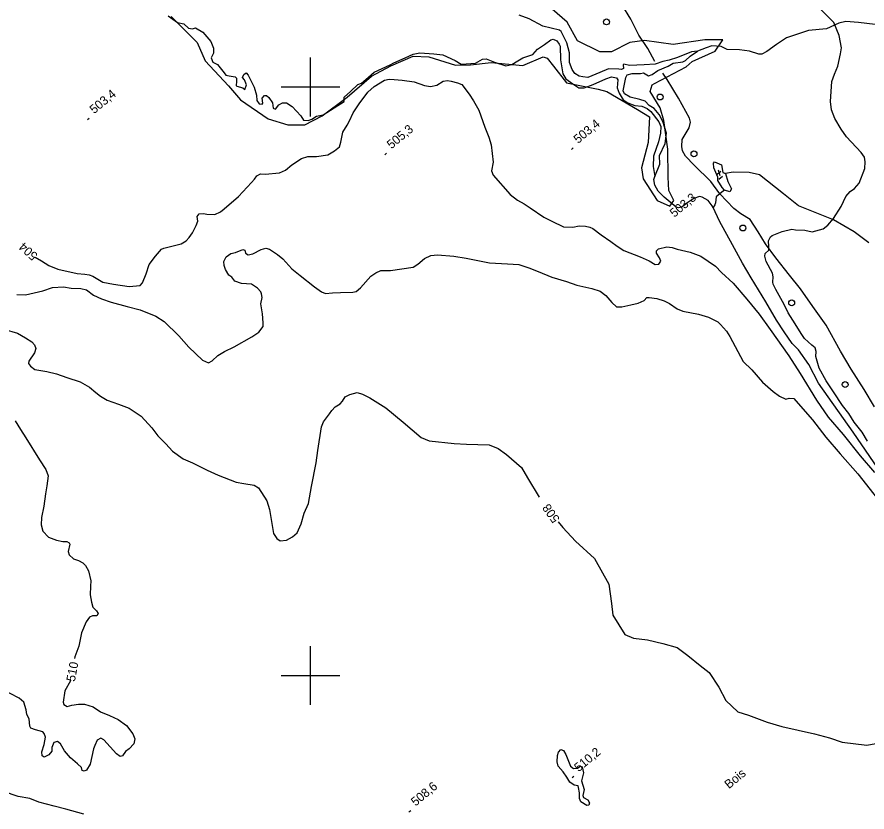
# Model space of a CAD drawing. Extents: x 347059 to 352153, y 6073752 to 6078601.
# Drawn here: x 348150.4 to 348583.7, y 6076130.4 to 6076535.6 of the extents above; entities that cross this region are included whole.
import ezdxf

# ---------------------------------------------------------------- set-up
doc = ezdxf.new("R2010")
doc.units = 0
for name, color, linetype in [('Level 1', 7, 'Continuous'), ('Level 2', 7, 'Continuous'), ('Level 22', 7, 'Continuous'), ('Level 3', 7, 'Continuous'), ('Level 36', 7, 'Continuous'), ('Level 4', 7, 'Continuous'), ('Level 44', 7, 'Continuous'), ('Level 61', 7, 'Continuous')]:
    doc.layers.add(name, color=color, linetype=linetype)

msp = doc.modelspace()

# ---------------------------------------------------------------- linework, layer by layer
at = {"layer": 'Level 1'}
for points in [[(348149.41, 6076329.83), (348152.14, 6076325.41), (348154.95, 6076321.2), (348161.89, 6076309.85), (348165.02, 6076304.97), (348166.31, 6076301.74), (348165.64, 6076296.69), (348164.83, 6076292.61), (348164, 6076286.33), (348162.91, 6076280.52), (348162.77, 6076276.74), (348163.63, 6076273.55), (348166.45, 6076270.43), (348170.56, 6076268.97), (348173.78, 6076268.22), (348175.83, 6076268.36), (348176.94, 6076267.7), (348177.32, 6076266.94), (348176.39, 6076263.15), (348176.92, 6076261.58), (348179.1, 6076259.53), (348181.8, 6076258.61), (348183.97, 6076257.5), (348185.24, 6076256.02), (348186.86, 6076253.36), (348188.09, 6076248.32), (348187.88, 6076245.57), (348187.7, 6076241.07)], [(348187.7, 6076241.07), (348188.29, 6076237.38), (348189.05, 6076234.78), (348190.94, 6076232.89), (348191.72, 6076231.53), (348191.13, 6076230.48), (348188.93, 6076230.35), (348187.37, 6076229.81), (348185.66, 6076227.39), (348183.34, 6076221.73), (348181.89, 6076214.92), (348179.89, 6076209.54), (348179.73, 6076208.6)], [(348177.72, 6076197.59), (348177.67, 6076197.33), (348174.74, 6076192.23), (348173.88, 6076186.47), (348174.23, 6076185.28), (348175.9, 6076184.29), (348178.41, 6076184.83), (348181.65, 6076185.32), (348184.86, 6076185.37), (348189.2, 6076184.1), (348193.02, 6076181.56), (348197.45, 6076179.56), (348202.03, 6076177.55), (348206.17, 6076174.48), (348209.5, 6076170.3), (348210.4, 6076167.68), (348209.92, 6076165.1), (348207.62, 6076162.58), (348205.69, 6076161.19), (348204.15, 6076159.05), (348202.89, 6076158.78), (348201.17, 6076160.14), (348197.94, 6076163.58), (348194.64, 6076167.25), (348193.03, 6076168.02), (348191.28, 6076167.06), (348190.06, 6076164.39), (348189.34, 6076162.55), (348187.68, 6076154.88), (348185.85, 6076151.81), (348184.57, 6076151.25), (348183.65, 6076151.54), (348183.19, 6076153.18), (348181.28, 6076154.92), (348177.58, 6076157.96), (348174.51, 6076161.68), (348172.58, 6076165.17), (348171, 6076166.38), (348169.22, 6076165.93), (348168.16, 6076163.39), (348168.08, 6076161.43), (348166.64, 6076159.64), (348164.29, 6076158.43), (348163.18, 6076159.1), (348162.96, 6076161.08), (348164.19, 6076164.85), (348164.97, 6076168.5), (348164.24, 6076170.45), (348163.57, 6076171.22), (348159.73, 6076172.38), (348157.39, 6076173.21), (348156.88, 6076174.12), (348156.5, 6076177.86)], [(348156.5, 6076177.86), (348155.36, 6076180.13), (348155.1, 6076182.48), (348153.79, 6076186.36), (348151.47, 6076188.42), (348142.36, 6076193.17)], [(348428.87, 6076150.93), (348426.3, 6076153.75), (348425.67, 6076156.05), (348425.91, 6076159.24), (348426.33, 6076160.96), (348427.52, 6076162.26), (348428.95, 6076161.86), (348430.19, 6076159.8), (348432.51, 6076153.8), (348434.1, 6076152.59), (348436.16, 6076152.73), (348437.63, 6076153.86), (348438.48, 6076153.5), (348439.12, 6076150.39), (348438.48, 6076147.67), (348438.09, 6076146.39), (348439.43, 6076141.84), (348438.77, 6076138.83), (348439.13, 6076137.78), (348441.38, 6076136.59), (348442.28, 6076135.07), (348441.91, 6076133.93), (348440.8, 6076133.79), (348437.8, 6076135.69), (348437.12, 6076137.27), (348437.11, 6076140.12), (348436.67, 6076142.99), (348436.37, 6076143.82), (348434.41, 6076144.03), (348432.27, 6076145.72), (348430.64, 6076148.25), (348428.87, 6076150.93)]]:
    msp.add_lwpolyline(points, dxfattribs=at)
at = {"layer": 'Level 2'}
for points in [[(348579.7, 6076450.91), (348582.54, 6076458.4), (348582.79, 6076461.76), (348582.46, 6076464.2), (348580.72, 6076466.53), (348573.16, 6076474.48), (348570.45, 6076478.41), (348567.33, 6076483.91), (348565.53, 6076488.37), (348565.11, 6076492.5), (348565.8, 6076502.79), (348567.03, 6076506.44), (348568.88, 6076510.49), (348570.23, 6076516.84), (348570.61, 6076519.89), (348569.47, 6076526.28), (348566.81, 6076532.85), (348562.83, 6076536.65), (348556.15, 6076543.58), (348553.8, 6076546.61), (348552.44, 6076548.98), (348551.14, 6076550.32)], [(348159.68, 6076413.27), (348162.95, 6076411.28), (348166.66, 6076409.04), (348171.27, 6076407.17), (348181.12, 6076404.92), (348184.97, 6076404.57), (348187.21, 6076404.19), (348189.05, 6076403.47), (348194.09, 6076400.47), (348199.65, 6076399.41), (348207.54, 6076398.32), (348213.2, 6076398.71), (348214.4, 6076400.16), (348216.14, 6076404.79), (348217.72, 6076409.43), (348220.9, 6076413.81), (348224.08, 6076417.24), (348225.3, 6076417.88), (348234.09, 6076420.02), (348236.62, 6076421.52), (348238.07, 6076423.32), (348239.78, 6076425.61), (348241.74, 6076429.34), (348242.49, 6076431.63), (348242.15, 6076433.92), (348243.28, 6076435.31), (348245.42, 6076435.52), (348247.22, 6076435.17), (348251.23, 6076434.95), (348254.04, 6076436.28), (348255.98, 6076437.83), (348263.25, 6076444.1), (348269.86, 6076451.31), (348271.45, 6076452.95), (348272.6, 6076454.62), (348274.58, 6076455.65), (348276.91, 6076455.48), (348284.21, 6076456.2), (348287.24, 6076457.59), (348290.45, 6076460.36), (348295.37, 6076463.52), (348298.66, 6076464.45), (348303.13, 6076464.49), (348308.76, 6076465.41), (348312.21, 6076467.43), (348314.7, 6076469.44), (348315.47, 6076471.88), (348316.43, 6076476.93), (348318.67, 6076480.5), (348319.93, 6076482.68), (348321.78, 6076486.86), (348324.75, 6076491.34), (348329.3, 6076497.3), (348332.52, 6076500.22), (348337.74, 6076503.36), (348340.12, 6076503.92), (348342.68, 6076503.81), (348346.76, 6076503.51), (348352.77, 6076502.57), (348358.05, 6076500.73), (348361.17, 6076500.28)], [(348361.17, 6076500.28), (348364.36, 6076500.86), (348367.6, 6076502.97), (348369.89, 6076503.31), (348371.7, 6076502.97), (348374.93, 6076502.07), (348377.21, 6076501.18), (348380.88, 6076496.3), (348383.11, 6076492.92), (348385.84, 6076488.18), (348388.79, 6076479.55), (348390.96, 6076474.34), (348392.07, 6076470.52), (348393.09, 6076461.59), (348392.33, 6076457.25), (348393.04, 6076455), (348401.76, 6076445.22), (348405.57, 6076442.23), (348408.89, 6076440.46), (348412.03, 6076438.4), (348419.01, 6076433.65), (348423.03, 6076431.52), (348428.9, 6076428.68), (348433.73, 6076428.48), (348437, 6076429.12), (348440.22, 6076429.04), (348442.39, 6076428.59), (348443.95, 6076427.89), (348448.11, 6076424.66), (348453.07, 6076421.29), (348456.33, 6076418.79), (348459.76, 6076416.56), (348468.1, 6076413.39), (348472.64, 6076411.31), (348475.67, 6076409.55), (348477.59, 6076409.7), (348478.5, 6076411.17), (348477.82, 6076412.91), (348476.38, 6076415.21), (348476.4, 6076416.45), (348477.43, 6076417.48), (348481.68, 6076418.42), (348484.3, 6076418.08), (348486.89, 6076417.31)], [(348583.99, 6076319.52), (348581.24, 6076323.97), (348577.14, 6076329.18), (348574.38, 6076333.49), (348571.16, 6076337.54), (348566.61, 6076344.54), (348562.78, 6076350.24), (348559.29, 6076356.65), (348557.6, 6076362.56), (348557.8, 6076365.19), (348557.2, 6076366.99), (348555.54, 6076368.43), (348551.83, 6076371.78), (348550.1, 6076374.25), (348547.03, 6076379.24), (348543.47, 6076384.77), (348541.45, 6076389.17), (348537.18, 6076396.81), (348535.76, 6076399.41), (348535.62, 6076400.51), (348535.81, 6076403.14), (348535.45, 6076405.14), (348532.29, 6076411.02), (348531.61, 6076413.7), (348531.71, 6076415.02), (348533.7, 6076416.73), (348533.67, 6076418.61), (348533.45, 6076421.56), (348534.55, 6076423.61), (348535.41, 6076424.2), (348540.41, 6076426.33), (348545.34, 6076427.44), (348547.3, 6076427.08), (348552.06, 6076426.96), (348555.67, 6076426.11), (348561.29, 6076427.68), (348563.78, 6076429.55), (348566.61, 6076432.94), (348570.44, 6076438.97), (348572.81, 6076444.15), (348575.05, 6076446.63), (348577.23, 6076448.23), (348579.7, 6076450.91)], [(348275.9, 6076379.82), (348275.51, 6076384.38), (348274.72, 6076389.4), (348275.33, 6076392.65), (348274.95, 6076394.5), (348274.66, 6076395.47), (348273.06, 6076397.49), (348269.91, 6076399.39), (348264.9, 6076399.83), (348261.48, 6076400.96), (348259.81, 6076403.05), (348258.35, 6076404.11), (348256.65, 6076406.86), (348255.93, 6076408.96), (348255.87, 6076411.08), (348256.92, 6076413.34), (348259.46, 6076415.13), (348261.69, 6076415.55), (348265.53, 6076417.1), (348266.52, 6076416.74), (348266.78, 6076415.33), (348268.25, 6076414.42), (348270.55, 6076414.91), (348274.89, 6076417.15), (348277.28, 6076417.86), (348279.13, 6076417.28), (348283.18, 6076414.65), (348285.93, 6076412.41), (348290.45, 6076407.33), (348294.8, 6076403.87), (348302.05, 6076398.16), (348305.58, 6076395.49), (348307.72, 6076394.75), (348311.25, 6076395.08), (348315.21, 6076395.23), (348321.59, 6076395.42), (348323.29, 6076395.67), (348325.55, 6076397.62)], [(348486.89, 6076417.31), (348493.59, 6076415.72), (348498.95, 6076413.8), (348506.42, 6076408.64), (348509.56, 6076405.48), (348515.46, 6076399.92), (348522.34, 6076391.8), (348528.75, 6076384.23), (348534.26, 6076376.43), (348543.83, 6076362.98), (348549.54, 6076353.99), (348557.86, 6076340.41), (348563.81, 6076331.62), (348571.53, 6076322.85), (348580.2, 6076312.03), (348587.57, 6076303.5)], [(348325.55, 6076397.62), (348330.67, 6076403.54), (348333.22, 6076405.32), (348335.86, 6076406.38), (348340.84, 6076406.45), (348352.3, 6076408.18), (348354.75, 6076409.61), (348358.11, 6076412.51), (348361.3, 6076414.03), (348364.77, 6076414.44), (348372.98, 6076413.77), (348379.41, 6076412.65), (348391.32, 6076410.4), (348400.42, 6076409.81), (348406.18, 6076409.47), (348411.25, 6076407.71), (348416.02, 6076405.97), (348422.97, 6076402.98), (348430.57, 6076400.82), (348435.71, 6076398.99), (348443.42, 6076397.33), (348447.7, 6076395.85), (348450.48, 6076393.75), (348453.64, 6076390.08), (348455.9, 6076387.94), (348458.76, 6076387.96), (348463.29, 6076388.87), (348467.02, 6076389.77), (348470.06, 6076391.16), (348471.49, 6076392.66), (348472.67, 6076392.72), (348476.51, 6076392.23), (348480.3, 6076391), (348483.05, 6076389.56), (348486.88, 6076386.87), (348489.72, 6076385.64), (348497.75, 6076384.25), (348502.9, 6076382.56), (348507.71, 6076380.31), (348509.01, 6076378.97)], [(348150.35, 6076394.2), (348154.78, 6076393.95), (348163.62, 6076396.01), (348168.42, 6076397.71), (348174.13, 6076398.02), (348178.03, 6076397.45), (348182.91, 6076397.31), (348185.77, 6076396.52), (348189.38, 6076393.92), (348193.39, 6076391.95), (348198.38, 6076390.27), (348206.46, 6076388.01), (348213.2, 6076386.35), (348221.22, 6076383.21), (348225.32, 6076380.5), (348232.95, 6076373.08), (348238.01, 6076367.38), (348244.88, 6076360.67), (348248.01, 6076359.42), (348249.9, 6076360.38), (348252.74, 6076363.09), (348256.11, 6076365.18), (348261.11, 6076367.6), (348270.11, 6076372.64), (348273.72, 6076375.08), (348275.91, 6076377.92), (348275.9, 6076379.82)], [(348143.72, 6076376.59), (348150.7, 6076374.48), (348154.75, 6076372.15)], [(348509.01, 6076378.97), (348511.98, 6076375.53), (348513.67, 6076372.78), (348520.49, 6076359.99), (348524.94, 6076355.79), (348530.48, 6076349.53), (348535.91, 6076344.67), (348539.11, 6076342.39), (348542.22, 6076340.84), (348544.02, 6076341.3), (348546.35, 6076341.13), (348548.66, 6076338.62), (348555.88, 6076330.26), (348562.63, 6076321.5), (348570.07, 6076313.05), (348579.06, 6076302.81), (348588.96, 6076290.08)], [(348154.75, 6076372.15), (348157.88, 6076370.1), (348159.29, 6076368.46), (348159.95, 6076366.59), (348159.29, 6076364.53), (348156.34, 6076360.22), (348156.32, 6076358.98), (348157.24, 6076357.6), (348159.53, 6076356.05), (348165.57, 6076355.03), (348170.44, 6076353.8), (348175.84, 6076351.95), (348182.52, 6076349.71), (348187.28, 6076347.03), (348190.57, 6076344.17), (348192.91, 6076342.39), (348196.26, 6076340.4), (348202.09, 6076338.37), (348207.62, 6076336.21), (348213.73, 6076332.12), (348219.05, 6076326.26), (348222.24, 6076322.09), (348226.17, 6076318.01), (348229.69, 6076314.4), (348235.16, 6076310.43), (348239.81, 6076308.34), (348247.27, 6076304.58), (348252.99, 6076302.05), (348262.13, 6076298.54), (348266.02, 6076297.81), (348271.29, 6076297.06), (348273.52, 6076295.59), (348277.7, 6076289.01), (348279.11, 6076284.53), (348281.2, 6076272.34), (348282.77, 6076269.89), (348284.5, 6076268.67), (348287.74, 6076269.01), (348290.78, 6076270.69), (348293.12, 6076272.7), (348295.22, 6076277.36), (348296.79, 6076282.79), (348298.91, 6076287.75), (348300.58, 6076296.38), (348302.86, 6076308.4), (348303.76, 6076314.6), (348305.62, 6076326.8), (348306.69, 6076329.35), (348309.61, 6076333.37), (348310.84, 6076335.1), (348312.65, 6076336.94), (348315.17, 6076338.43), (348316.38, 6076339.88), (348317.7, 6076341.97), (348319.99, 6076343.26), (348323.72, 6076344.3), (348326.42, 6076343.38), (348330.22, 6076341.49), (348338.32, 6076336.43), (348347.25, 6076329.2), (348356.49, 6076321.26), (348360.48, 6076319.65), (348373.21, 6076318.27), (348379.53, 6076317.89), (348391.05, 6076317.59)], [(348391.05, 6076317.59), (348395.7, 6076315.72), (348399.85, 6076312.67), (348407.48, 6076306.01), (348410.53, 6076300.69), (348416.63, 6076290.87)], [(348426.22, 6076278.3), (348428.61, 6076275.37), (348435.16, 6076268.48), (348444.84, 6076259.65), (348452.05, 6076246.62), (348453.41, 6076236.62), (348454.05, 6076230.77), (348460.26, 6076220.88), (348464.66, 6076218.96), (348471.77, 6076218.19), (348479.59, 6076216.29), (348486.91, 6076214.2), (348492.32, 6076210.18), (348498.57, 6076205.16), (348503.16, 6076201.58), (348508.14, 6076194.05), (348511.69, 6076187.34), (348517.87, 6076181.51), (348523.18, 6076179.75), (348532.73, 6076176.16), (348540.24, 6076174.01), (348556.85, 6076170.22), (348564.58, 6076168.26), (348570.99, 6076166.08), (348583.59, 6076164.47), (348590.05, 6076165.72)]]:
    msp.add_lwpolyline(points, dxfattribs=at)
at = {"layer": 'Level 22'}
for points in [[(348475.53, 6076513.03), (348471.95, 6076519.53), (348467.38, 6076526.4), (348463.23, 6076534.46), (348458.68, 6076542.03), (348454.94, 6076548.54), (348449.63, 6076556.91), (348445.15, 6076563.4), (348442, 6076568.67), (348438.97, 6076574.34), (348436.39, 6076578.65), (348434.44, 6076582.57)], [(348587.41, 6076336.94), (348582.21, 6076345.8), (348575.54, 6076356.15), (348570.15, 6076365.24), (348562.79, 6076378.55), (348556.13, 6076388.08), (348549.82, 6076397.01), (348544.1, 6076404.09), (348537.25, 6076412.95), (348531.97, 6076419.95), (348528.2, 6076426.13), (348524.11, 6076432.34), (348519.38, 6076435.29), (348515.85, 6076438.05), (348508.58, 6076445.52), (348504.14, 6076451.72), (348495.53, 6076460.16), (348491.22, 6076464.75), (348489.57, 6076467.44), (348489.3, 6076469.63), (348489.44, 6076473.14), (348493.09, 6076479.17), (348493.62, 6076482.03), (348493.22, 6076484.03), (348487.5, 6076494.18), (348481.77, 6076503.78), (348479.62, 6076506.95)], [(348184.42, 6076129.32), (348175.2, 6076131.94), (348169.4, 6076133.38), (348161.45, 6076135.46), (348156.87, 6076137.33), (348150.91, 6076138.41), (348143.49, 6076140.96)]]:
    msp.add_lwpolyline(points, dxfattribs=at)
at = {"layer": 'Level 3'}
for p, q in [((348186.33, 6076483.33), (348187.25, 6076484.1)), ((348433.03, 6076468.17), (348433.95, 6076468.94)), ((348337.85, 6076465.42), (348338.77, 6076466.19)), ((348507.36, 6076455.52), (348509.17, 6076457.01)), ((348507.82, 6076457.65), (348508.65, 6076454.9)), ((348508.08, 6076453), (348509.93, 6076454.53)), ((348433.34, 6076147.94), (348434.26, 6076148.71)), ((348350.16, 6076130.47), (348351.08, 6076131.24))]:
    msp.add_line(p, q, dxfattribs=at)
at = {"layer": 'Level 36'}
for centre in [(348450.88, 6076533.12), (348478.22, 6076494.87), (348495.47, 6076465.86), (348520.39, 6076428.08), (348545.27, 6076389.91), (348572.55, 6076348.28)]:
    msp.add_circle(centre, 1.5, dxfattribs=at)
at = {"layer": 'Level 4'}
for points in [[(348227.44, 6076536.16), (348232.24, 6076532.79), (348235.5, 6076532.14), (348237.74, 6076529.93), (348239.8, 6076529.63), (348241.36, 6076530.11), (348245.03, 6076527.9), (348249.14, 6076523.19), (348250.52, 6076519.67), (348250.47, 6076517.21), (348249.28, 6076514.77), (348250.29, 6076512.67), (348252.61, 6076511.45), (348255.94, 6076507.22), (348256.86, 6076506.03), (348258.55, 6076505.64), (348261.59, 6076505.17)], [(348479.56, 6076482.43), (348477.72, 6076485.87), (348475.12, 6076488.96), (348472.67, 6076490.45), (348470.57, 6076492.76), (348467.94, 6076493.56), (348462.98, 6076494.81), (348460.13, 6076496.42), (348459.4, 6076497.99), (348460.66, 6076504.73), (348461.48, 6076506.09), (348463.91, 6076506.78), (348468.29, 6076506.85), (348469.71, 6076507.22), (348472.35, 6076505.59), (348474.21, 6076506.25), (348477.05, 6076508.34), (348482.31, 6076510.58), (348484.85, 6076512.12), (348489.74, 6076512.85), (348491.13, 6076513.42), (348493.5, 6076515.71), (348497.35, 6076518.2), (348494.21, 6076517.82), (348487.05, 6076514.96), (348482.85, 6076513.61), (348479.68, 6076512.9), (348475.64, 6076511.53), (348470.05, 6076511.28), (348462.53, 6076510.83), (348459.77, 6076511.61), (348459.38, 6076511.27), (348459.51, 6076509.42), (348458.6, 6076508.88), (348457.1, 6076508.97), (348451.88, 6076509.18), (348447.54, 6076507.26), (348441.28, 6076504.86), (348438.85, 6076505.07), (348436.87, 6076505.45), (348434.82, 6076506.81), (348433.32, 6076508.95), (348431.99, 6076512.51), (348431.95, 6076517.39), (348430.58, 6076522.51), (348427.79, 6076528.16), (348426.95, 6076528.89), (348418.49, 6076530.98), (348411.48, 6076534.67), (348406.28, 6076536.64)], [(348587.83, 6076531.75), (348579.4, 6076532.85), (348572.82, 6076533.26), (348569.24, 6076532.43), (348563.05, 6076529.62), (348553.87, 6076528.74), (348542.64, 6076524.93), (348537.5, 6076521.58), (348532.54, 6076518), (348530.14, 6076516.65), (348528.54, 6076516.67), (348523.74, 6076518.27), (348518.64, 6076518.88), (348512.44, 6076519.1), (348509.26, 6076520.56), (348504.5, 6076520.85), (348501.64, 6076519.96), (348497.35, 6076518.2)], [(348362.8, 6076516.78), (348367.4, 6076516.42), (348373.66, 6076513.54), (348376.78, 6076511.62), (348379.28, 6076511.69), (348384.06, 6076512.1), (348387.64, 6076514.2), (348389.57, 6076514.32), (348393.81, 6076512.6), (348399.54, 6076510.71), (348402.59, 6076511.38), (348405.66, 6076513.37), (348408.2, 6076514.83), (348413.3, 6076516.56), (348415.78, 6076519.25), (348419.33, 6076521.56), (348422.52, 6076523.95), (348423.66, 6076524.38), (348425.54, 6076523.4), (348426.68, 6076521.78), (348427.32, 6076520.74), (348427.51, 6076513.72), (348428.63, 6076506.74), (348430.22, 6076504.14), (348433.69, 6076501.63), (348436.82, 6076499.51), (348439.49, 6076499.56), (348444.13, 6076501.29), (348450.51, 6076504.1), (348453.5, 6076505.19), (348456.03, 6076504.6), (348456.68, 6076503.56), (348456.38, 6076499.53), (348457.29, 6076496.74), (348459.42, 6076493.4), (348461.67, 6076491.9), (348465.39, 6076490.51), (348468.89, 6076490.2), (348471.61, 6076489.02), (348473.52, 6076487.46), (348477.49, 6076482.12), (348478.52, 6076479.82), (348478.47, 6076476.38), (348477.33, 6076472.01), (348474.91, 6076464.77), (348474.71, 6076459.46), (348475.51, 6076454.39), (348478.08, 6076460.56), (348477.92, 6076464.96), (348480.86, 6076471.22), (348481.38, 6076476.41), (348479.56, 6076482.43)], [(348261.59, 6076505.17), (348262.35, 6076504.45), (348262.24, 6076502.69), (348262.03, 6076500.7), (348262.36, 6076500.3), (348265.57, 6076499.45), (348266.45, 6076498.68), (348267.39, 6076501.14), (348266.33, 6076503.57), (348265.41, 6076504.75), (348265.99, 6076506.3), (348267.17, 6076507.14), (348268.25, 6076505.94), (348271.22, 6076499.82), (348272.44, 6076495.86), (348272.65, 6076493.01), (348273.86, 6076491.3), (348275.28, 6076491.14), (348275.66, 6076491.76), (348275.41, 6076494.2), (348276.47, 6076495.55), (348277.55, 6076495.7), (348278.77, 6076494.61), (348280.55, 6076491.87), (348281.01, 6076489.08), (348282.2, 6076488.65), (348283.83, 6076490.93), (348285.71, 6076491.91), (348287.84, 6076491.89), (348290.63, 6076489.93), (348295.02, 6076485.24), (348296.48, 6076483.06), (348298.84, 6076482.86), (348300.65, 6076483.48), (348303.05, 6076485.12), (348306.43, 6076485.85), (348310.14, 6076488.07), (348317.08, 6076492.63), (348317.19, 6076494.84), (348320.42, 6076497.71), (348324.05, 6076501.29), (348325.99, 6076501.94), (348328.16, 6076503.85), (348332.52, 6076507.44), (348340.67, 6076511.29), (348342.46, 6076512.19), (348348.26, 6076514.89), (348352.27, 6076516.75), (348355.8, 6076517.31), (348362.8, 6076516.78)], [(348513.73, 6076446.46), (348511.11, 6076447.35), (348509.79, 6076448.65), (348507.65, 6076452.36), (348507.55, 6076454.08), (348505.62, 6076458.8), (348505.45, 6076461.15), (348505.95, 6076461.8), (348509.42, 6076460.27), (348510.12, 6076456.4), (348511.46, 6076455.87), (348512.75, 6076451.75), (348514.52, 6076448.11), (348513.73, 6076446.46)], [(348593.64, 6076299.17), (348576.64, 6076324.03), (348558.99, 6076348.96), (348554.08, 6076358.56), (348548.83, 6076366.05), (348545.58, 6076369.2), (348541.43, 6076375.21), (348537.51, 6076381.03), (348532.05, 6076390.39), (348524.63, 6076402.62), (348520.23, 6076410.09), (348515.06, 6076419.47), (348508.48, 6076431.59), (348505.18, 6076438.49), (348504.73, 6076439.45), (348502.78, 6076442.03), (348499.7, 6076443.82), (348498.26, 6076444.19), (348495.43, 6076443.08), (348492.27, 6076441.1), (348489.43, 6076438.85), (348487.63, 6076438.39), (348486.31, 6076438.79), (348480.2, 6076443.83), (348477.28, 6076446.82), (348475.46, 6076449.89), (348475.05, 6076452.79), (348475.51, 6076454.39)], [(348584.62, 6076420.48), (348577.1, 6076426.21), (348566.6, 6076432.27), (348548.83, 6076439.46), (348541.09, 6076445.45), (348528.83, 6076455.11), (348523.55, 6076456.39), (348515.47, 6076456.6), (348511.46, 6076455.87)], [(348511.11, 6076447.35), (348509.59, 6076446.29), (348508.58, 6076445.52), (348506.74, 6076443.96), (348506.44, 6076440.99), (348506.14, 6076439.83), (348505.18, 6076438.49)]]:
    msp.add_lwpolyline(points, dxfattribs=at)
at = {"layer": 'Level 44'}
msp.add_lwpolyline([(348228.91, 6076535.91), (348242.3, 6076522.69), (348246.25, 6076513.33), (348258.27, 6076500.48), (348264.39, 6076493.39), (348278.4, 6076483.72), (348288.46, 6076480.72), (348297.06, 6076480.71), (348305.96, 6076485.18), (348318.73, 6076494.72), (348331.1, 6076505.45), (348340.89, 6076510.82), (348352.27, 6076515.73), (348360.26, 6076515.36), (348373.98, 6076511.06), (348381.52, 6076511.22), (348392.09, 6076512.43), (348408.25, 6076510.94), (348418.59, 6076515.28), (348420.59, 6076514.69), (348423.92, 6076510.55), (348430.57, 6076502.11), (348446.65, 6076498.91), (348451.04, 6076497.63), (348466.61, 6076488.41), (348472.75, 6076484.68), (348472.14, 6076471.63), (348468.77, 6076458.83), (348469.51, 6076453.11), (348476.67, 6076442.09), (348483.21, 6076439.15), (348485.18, 6076442.17), (348482.58, 6076447.23), (348482.33, 6076453.96), (348482.16, 6076468.31), (348480.19, 6076482.81), (348478.21, 6076489.29), (348473.11, 6076497.68), (348474.14, 6076501.11), (348475.33, 6076501.66), (348491.5, 6076510.16), (348494.52, 6076513.01), (348506.24, 6076518.21), (348510.24, 6076524), (348501, 6076523.91), (348484.87, 6076521.63), (348470.24, 6076523.64), (348462.8, 6076522.65), (348453.4, 6076517.91), (348447.51, 6076517.93), (348436.12, 6076523.43), (348430.8, 6076532.98), (348423.17, 6076539.54)], dxfattribs=at)
at = {"layer": 'Level 61'}
for p, q in [((348300, 6076485), (348300, 6076515)), ((348285, 6076500), (348315, 6076500)), ((348300, 6076185), (348300, 6076215)), ((348285, 6076200), (348315, 6076200))]:
    msp.add_line(p, q, dxfattribs=at)

# ---------------------------------------------------------------- texts
at = {"layer": 'Level 1'}
msp.add_text('510', height=4.5, rotation=79.3122, dxfattribs=at).set_placement((348179.86, 6076196.65))
at = {"layer": 'Level 2'}
for s, rotation, p in [('504', 137.9741, (348161.3, 6076414.44)), ('508', 125.0296, (348427.29, 6076279.79))]:
    msp.add_text(s, height=4.5, rotation=rotation, dxfattribs=at).set_placement(p)
at = {"layer": 'Level 3'}
for s, rotation, p in [('503,4', 39.62, (348189.69, 6076486.04)), ('505,3', 39.62, (348341.21, 6076468.14)), ('503,4', 39.62, (348436.39, 6076470.88)), ('  503,3', 39.57, (348482.87, 6076431.14)), ('510,2', 39.62, (348436.7, 6076150.66)), ('508,6', 39.62, (348353.52, 6076133.18))]:
    msp.add_text(s, height=4.5, rotation=rotation, dxfattribs=at).set_placement(p)
at = {"layer": 'Level 44'}
msp.add_text('Bois', height=4.5, rotation=39.568, dxfattribs=at).set_placement((348513.3, 6076142.01))

doc.saveas('drawing.dxf')
